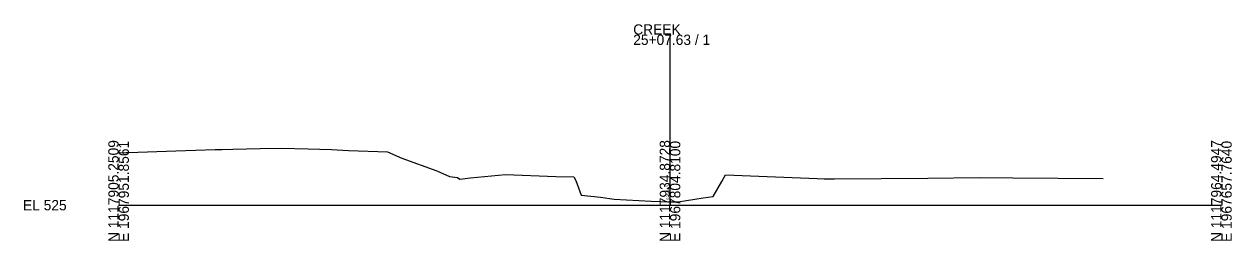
# Model space of a CAD drawing. Extents: x 9974 to 10303, y 9990 to 19550.
# Drawn here: x 9974.3 to 10302.8, y 14490.3 to 14549.2 of the extents above; entities that cross this region are included whole.
import ezdxf

# ---------------------------------------------------------------- set-up
doc = ezdxf.new("R2010")
doc.units = 0
for name, color, linetype in [('Level 10', 7, 'Continuous'), ('Level 60', 7, 'Continuous'), ('Level 63', 7, 'Continuous')]:
    doc.layers.add(name, color=color, linetype=linetype)

msp = doc.modelspace()

# ---------------------------------------------------------------- linework, layer by layer
at = {"layer": 'Level 60'}
for p, q in [((10002.71, 14514.36), (10015.55, 14514.81)), ((10015.55, 14514.81), (10026.26, 14515.12)), ((10026.26, 14515.12), (10028.16, 14515.17)), ((10028.16, 14515.17), (10031.03, 14515.23)), ((10031.03, 14515.23), (10038.51, 14515.38)), ((10038.51, 14515.38), (10044.18, 14515.46)), ((10044.18, 14515.46), (10051.53, 14515.35)), ((10051.53, 14515.35), (10057.93, 14515.12)), ((10057.93, 14515.12), (10062.53, 14514.86)), ((10062.53, 14514.86), (10073.13, 14514.47)), ((10000, 14514.21), (10002.1, 14514.34)), ((10002.1, 14514.34), (10002.71, 14514.36)), ((10073.13, 14514.47), (10077.08, 14512.74)), ((10077.08, 14512.74), (10086.61, 14509.38)), ((10086.61, 14509.38), (10090.02, 14507.78)), ((10095.7, 14507.47), (10105.28, 14508.38)), ((10105.28, 14508.38), (10118.93, 14507.79)), ((10164.07, 14506.45), (10165.11, 14508.25)), ((10165.11, 14508.25), (10183.2, 14507.52)), ((10090.02, 14507.78), (10092.18, 14507.53)), ((10092.18, 14507.53), (10092.83, 14507.09)), ((10092.83, 14507.09), (10095.7, 14507.47)), ((10118.93, 14507.79), (10123.86, 14507.7)), ((10123.86, 14507.7), (10124.34, 14506.7)), ((10124.34, 14506.7), (10125.87, 14502.75)), ((10161.71, 14502.39), (10164.07, 14506.45)), ((10183.2, 14507.52), (10190.03, 14507.25)), ((10190.03, 14507.25), (10191.98, 14507.18)), ((10191.98, 14507.18), (10194.75, 14507.19)), ((10194.75, 14507.19), (10220.16, 14507.32)), ((10220.16, 14507.32), (10234.17, 14507.49)), ((10234.17, 14507.49), (10243.23, 14507.45)), ((10243.23, 14507.45), (10267.81, 14507.29)), ((10125.87, 14502.75), (10131.05, 14502.18)), ((10131.05, 14502.18), (10134.79, 14501.59)), ((10134.79, 14501.59), (10144.87, 14501.07)), ((10152.23, 14500.88), (10159.06, 14501.99)), ((10159.06, 14501.99), (10161.71, 14502.39)), ((10144.87, 14501.07), (10150, 14500.94)), ((10150, 14500.94), (10152.23, 14500.88))]:
    msp.add_line(p, q, dxfattribs=at)
at = {"layer": 'Level 63'}
for p, q in [((10150, 14500), (10150, 14546.37)), ((10000, 14500), (10150, 14500)), ((10150, 14500), (10300, 14500))]:
    msp.add_line(p, q, dxfattribs=at)

# ---------------------------------------------------------------- texts
at = {"layer": 'Level 10'}
msp.add_text('525.940', height=0.8, rotation=90, dxfattribs=at).set_placement((10149.9, 14501.44))
at = {"layer": 'Level 63'}
for s, p in [('CREEK', (10140, 14546.37)), ('25+07.63 / 1', (10140, 14543.57)), ('EL 525', (9974, 14498.6))]:
    msp.add_text(s, height=2.8, dxfattribs=at).set_placement(p)
for s, p in [('N 1117905.2509', (10000, 14490)), ('E 1967951.8561', (10002.8, 14490)), ('N 1117934.8728', (10150, 14490)), ('E 1967804.8100', (10152.8, 14490)), ('N 1117964.4947', (10300, 14490)), ('E 1967657.7640', (10302.8, 14490))]:
    msp.add_text(s, height=2.8, rotation=90, dxfattribs=at).set_placement(p)

doc.saveas('drawing.dxf')
